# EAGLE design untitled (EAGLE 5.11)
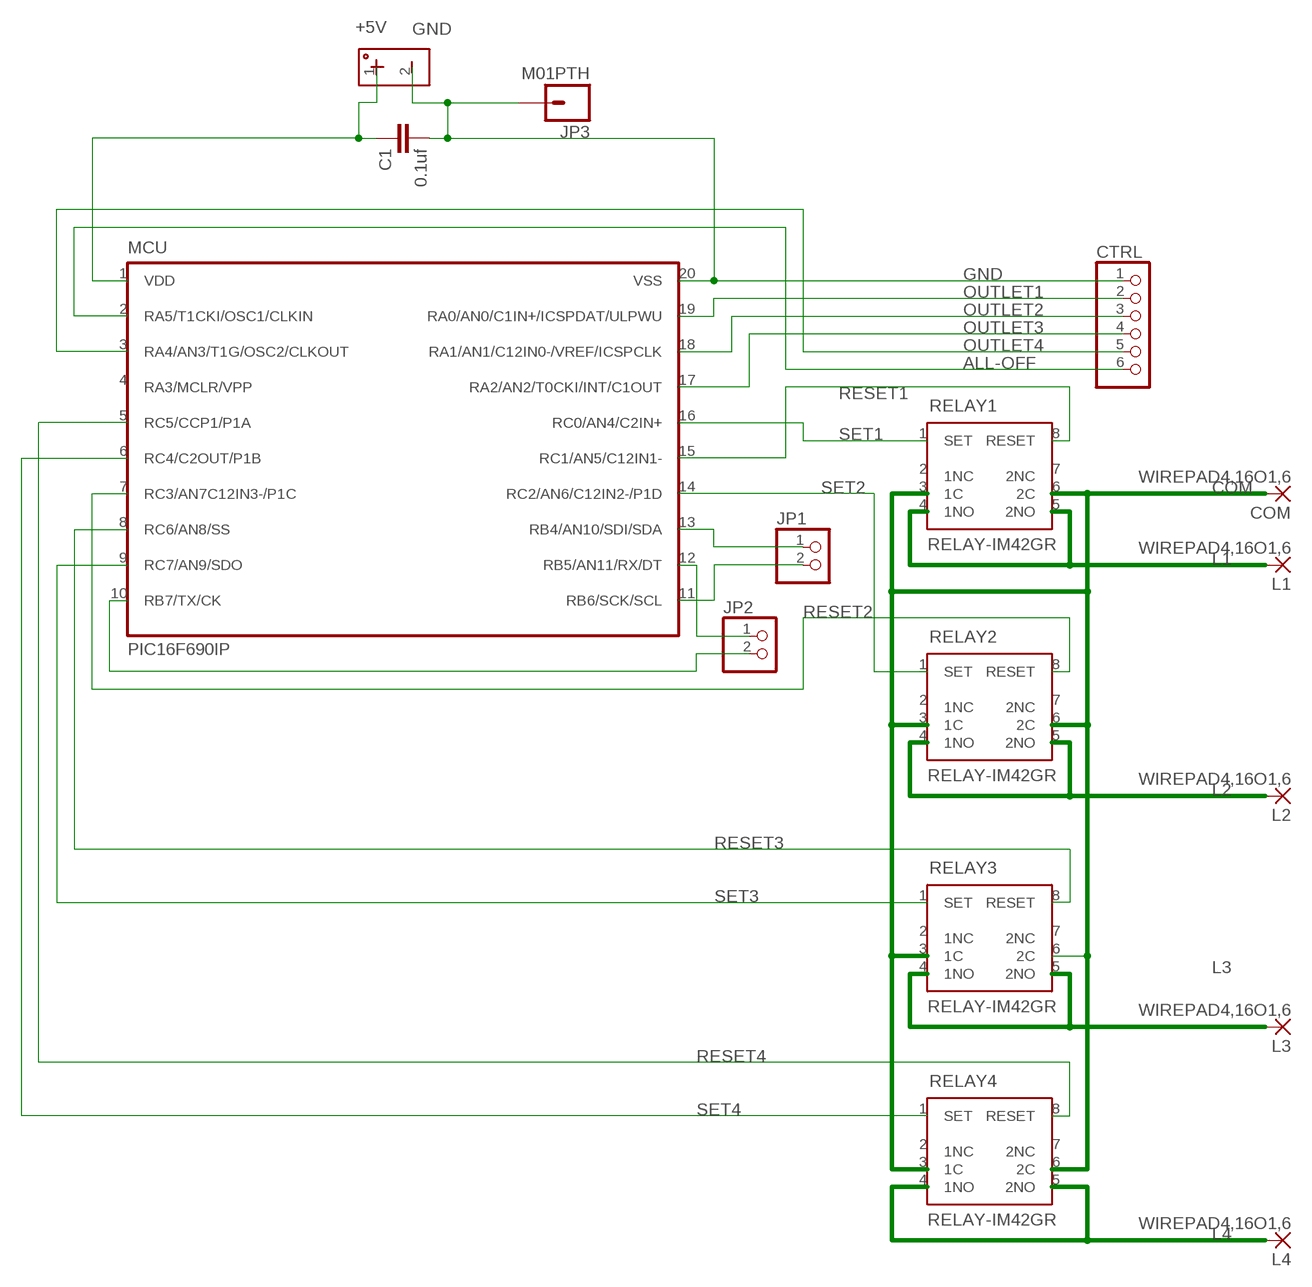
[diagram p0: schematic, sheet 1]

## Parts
+5V  HEADER-POWER  [HEADER-POWER-PTH]
C1  0.1uf  C-EU025-025X050  [C025-025X050]
COM  WIREPAD4,16O1,6  [4,16O1,6]
CTRL  PINHD-1X6  [1X06]
JP1  PINHD-1X2  [1X02]
JP2  PINHD-1X2  [1X02]
JP3  M01PTH  [1X01]
L1  WIREPAD4,16O1,6  [4,16O1,6]
L2  WIREPAD4,16O1,6  [4,16O1,6]
L3  WIREPAD4,16O1,6  [4,16O1,6]
L4  WIREPAD4,16O1,6  [4,16O1,6]
MCU  PIC16F690IP  [DIL20]
RELAY1  RELAY-IM42GR  [RELAY-IM42GR]
RELAY2  RELAY-IM42GR  [RELAY-IM42GR]
RELAY3  RELAY-IM42GR  [RELAY-IM42GR]
RELAY4  RELAY-IM42GR  [RELAY-IM42GR]

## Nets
+5V: +5V.1 C1.1 MCU.1(VDD)
ALL-OFF: CTRL.6 MCU.2(RA5/T1CKI/OSC1/CLKIN)
COM: COM.1(P) RELAY1.3(1C) RELAY1.6(2C) RELAY2.3(1C) RELAY2.6(2C) RELAY3.3(1C) RELAY3.6(2C) RELAY4.3(1C) RELAY4.6(2C)
GND: +5V.2 C1.2 CTRL.1 JP3.1 MCU.20(VSS)
L1: L1.1(P) RELAY1.4(1NO) RELAY1.5(2NO)
L2: L2.1(P) RELAY2.4(1NO) RELAY2.5(2NO)
L3: L3.1(P) RELAY3.4(1NO) RELAY3.5(2NO)
L4: L4.1(P) RELAY4.4(1NO) RELAY4.5(2NO)
N$1: JP1.1 MCU.13(RB4/AN10/SDI/SDA)
N$2: JP2.1 MCU.12(RB5/AN11/RX/DT)
N$3: JP1.2 MCU.11(RB6/SCK/SCL)
N$4: JP2.2 MCU.10(RB7/TX/CK)
OUTLET1: CTRL.2 MCU.19(RA0/AN0/C1IN+/ICSPDAT/ULPWU)
OUTLET2: CTRL.3 MCU.18(RA1/AN1/C12IN0-/VREF/ICSPCLK)
OUTLET3: CTRL.4 MCU.17(RA2/AN2/T0CKI/INT/C1OUT)
OUTLET4: CTRL.5 MCU.3(RA4/AN3/T1G/OSC2/CLKOUT)
RESET1: MCU.15(RC1/AN5/C12IN1-) RELAY1.8(RESET)
RESET2: MCU.7(RC3/AN7C12IN3-/P1C) RELAY2.8(RESET)
RESET3: MCU.8(RC6/AN8/SS) RELAY3.8(RESET)
RESET4: MCU.5(RC5/CCP1/P1A) RELAY4.8(RESET)
SET1: MCU.16(RC0/AN4/C2IN+) RELAY1.1(SET)
SET2: MCU.14(RC2/AN6/C12IN2-/P1D) RELAY2.1(SET)
SET3: MCU.9(RC7/AN9/SDO) RELAY3.1(SET)
SET4: MCU.6(RC4/C2OUT/P1B) RELAY4.1(SET)
Unconnected: MCU.4(RA3/MCLR/VPP) RELAY1.2(1NC) RELAY1.7(2NC) RELAY2.2(1NC) RELAY2.7(2NC) RELAY3.2(1NC) RELAY3.7(2NC) RELAY4.2(1NC) RELAY4.7(2NC)

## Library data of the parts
+5V = trl:HEADER-POWER
C1 = rcl:C-EU: CAPACITOR, European symbol
COM L1-L4 = wirepad:WIREPAD: Wire PAD connect wire on PCB
CTRL = pinhead:PINHD-1X6: PIN HEADER
JP1 JP2 = pinhead:PINHD-1X2: PIN HEADER
JP3 = SparkFun:M01: Header 1
MCU = trl:PIC16F690*: MICROCONTROLLER PIC16F690 18 I/O One 16-bit timer Two 8-bit timer Two comparators Precision internal oscillator-software selectable 8 MHz - 32 KHz SSP w/ I2C Compatible Address mask option EUSART LIN 2.0 Compatible ECCP+ w/ PWM Steering 12 A/D Channels ULPW Enhanced Low Power Timer 1 Timer 1 Gate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
RELAY1-RELAY4 = trl:RELAY-IM42GR

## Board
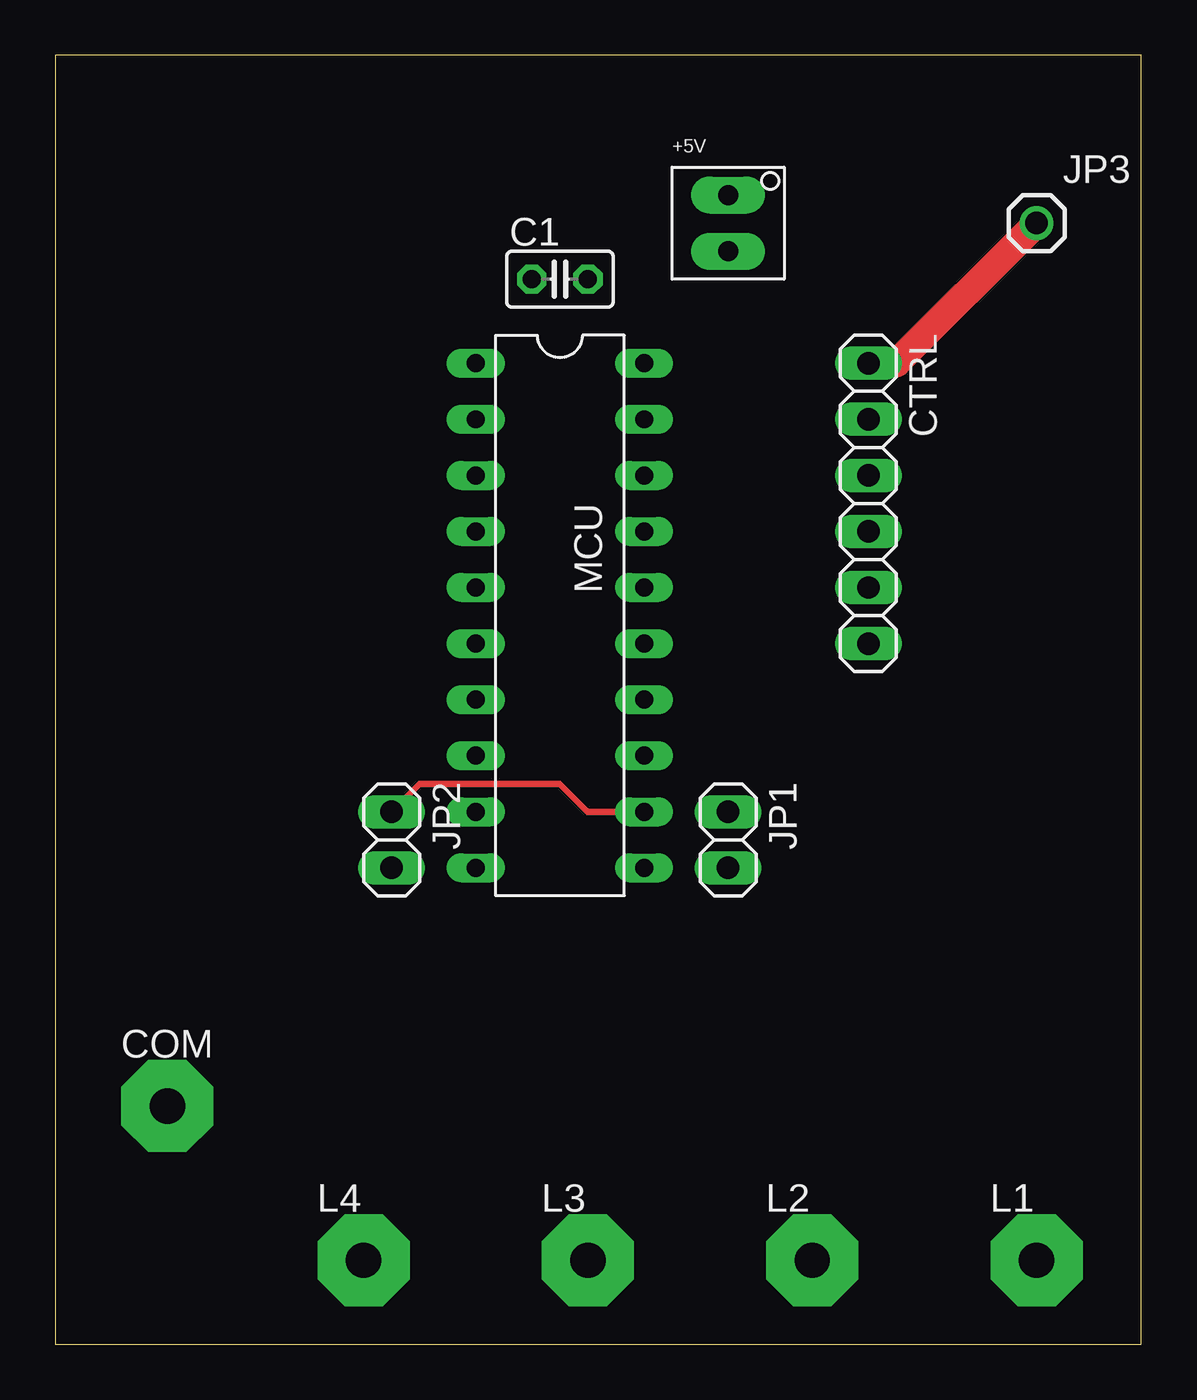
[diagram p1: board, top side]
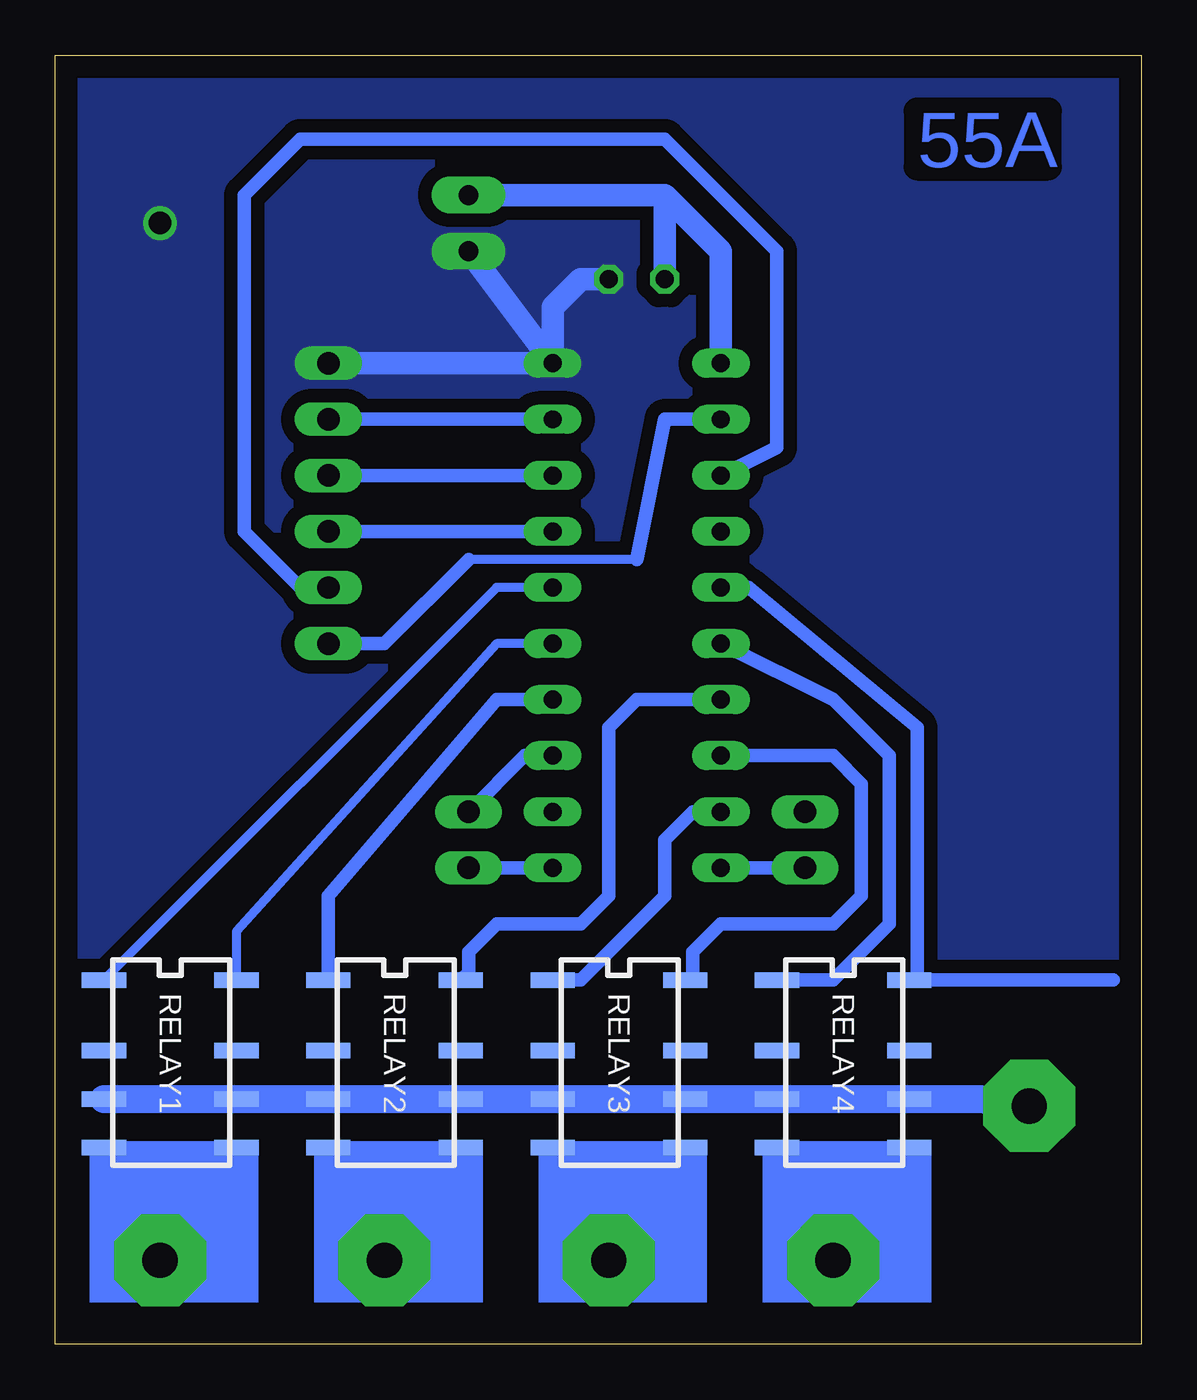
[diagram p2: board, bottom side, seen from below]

Size 49.2 x 58.41 mm. Coordinates in mm from the lower left corner, seen from the top.
Outline: 0,0 49.2,0 49.2,58.41 0,58.41 0,0
Copper layers (1*16): Top 0.035mm / dielectric 1.5mm / Bottom 0.035mm
Design rules "default": minimum track width 10mil, minimum drill 0.6mm, track to track 8mil, track to pad 8mil, pad to pad 8mil, via to via 8mil, smd to smd 8mil, copper to edge 40mil, drill to drill 8mil, minimum pad ring 10mil, minimum via ring 8mil, stop-mask expansion 4mil, vias tented up to drill 0mil, thermal gap 10mil

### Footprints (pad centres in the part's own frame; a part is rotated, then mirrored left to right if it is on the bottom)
HEADER-POWER-PTH = drill 0.9 pad 1.676 long: 1 0,1.27; 2 0,-1.27
C025-025X050 = drill 0.813 octagon: 1 -1.27,0; 2 1.27,0
4,16O1,6 = drill 1.6 pad 4.166 octagon: 1 0,0
1X06 = drill 1.016 long: 1 -6.35,0; 2 -3.81,0; 3 -1.27,0; 4 1.27,0; 5 3.81,0; 6 6.35,0
1X02 = drill 1.016 long: 1 -1.27,0; 2 1.27,0
1X01 = drill 1.016 round: 1 0,0
DIL20 = drill 0.813 long: 1 -11.43,-3.81; 2 -8.89,-3.81; 3 -6.35,-3.81; 4 -3.81,-3.81; 5 -1.27,-3.81; 6 1.27,-3.81; 7 3.81,-3.81; 8 6.35,-3.81; 9 8.89,-3.81; 10 11.43,-3.81; 11 11.43,3.81; 12 8.89,3.81; 13 6.35,3.81; 14 3.81,3.81; 15 1.27,3.81; 16 -1.27,3.81; 17 -3.81,3.81; 18 -6.35,3.81; 19 -8.89,3.81; 20 -11.43,3.81
RELAY-IM42GR = smd 2 x 0.7: 1 0,0; 2 0,-3.2; 3 0,-5.4; 4 0,-7.6; 5 6,-7.6; 6 6,-5.4; 7 6,-3.2; 8 6,0

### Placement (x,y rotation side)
+5V  30.48,50.8 0 top
C1  22.86,48.26 0 top
COM  5.08,10.79 0 top
CTRL  36.83,38.1 270 top
JP1  30.48,22.86 270 top
JP2  15.24,22.86 270 top
JP3  44.45,50.8 0 top
L1  44.45,3.81 0 top
L2  34.29,3.81 0 top
L3  24.13,3.81 0 top
L4  13.97,3.81 0 top
MCU  22.86,33.02 270 top
RELAY1  46.99,16.51 0 bottom
RELAY2  36.83,16.51 0 bottom
RELAY3  26.67,16.51 0 bottom
RELAY4  16.51,16.51 0 bottom

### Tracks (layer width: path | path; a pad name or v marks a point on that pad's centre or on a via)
+5V
  Bottom 1.016: 21.59,52.07 C1.1 | 21.59,52.07 +5V.1 | MCU.1 19.05,49.53 21.59,52.07
ALL-OFF
  Bottom 0.406: 22.86,35.56 30.48,35.56
  Bottom 0.61: CTRL.6 34.29,31.75 30.48,35.56 | 22.86,35.56 21.59,41.91 MCU.2
COM
  Bottom 0.813: RELAY1.3 RELAY1.6
  Bottom 1.27: RELAY1.3 RELAY2.3 RELAY2.6 RELAY3.3 RELAY3.6 RELAY4.3 RELAY4.6 7.3,11.11 COM.1
GND
  Top 1.27: CTRL.1 38.1,44.45 JP3.1
  Bottom 1.016: MCU.20 +5V.2 | C1.2 25.4,48.26 26.67,46.99 MCU.20 | MCU.20 CTRL.1
  pour Bottom (isolate 0.61, no thermals): 0,58.42 50.8,58.42 50.8,0 0,0
L1
  Bottom 0.61: RELAY1.5 RELAY1.4 46.99,6.35 L1.1
L2
  Bottom 0.61: RELAY2.5 RELAY2.4 36.83,6.35 L2.1
L3
  Bottom 0.61: RELAY3.5 RELAY3.4 26.67,6.35 L3.1
L4
  Bottom 0.61: RELAY4.5 RELAY4.4 16.51,6.35 L4.1
N$1
  Bottom 0.61: MCU.13 27.94,26.67 JP1.1
N$2
  Top 0.305: MCU.12 24.13,24.13 22.86,25.4 16.51,25.4 JP2.1
N$3
  Bottom 0.61: MCU.11 JP1.2
N$4
  Bottom 0.61: JP2.2 MCU.10
OUTLET1
  Bottom 0.61: MCU.19 CTRL.2
OUTLET2
  Bottom 0.61: MCU.18 CTRL.3
OUTLET3
  Bottom 0.61: MCU.17 CTRL.4
OUTLET4
  Bottom 0.61: CTRL.5 38.1,34.29 40.64,36.83 40.64,52.07 38.1,54.61 21.59,54.61 16.51,49.53 16.51,40.64 MCU.3
RESET1
  Bottom 0.406: RELAY1.8 40.99,18.7 29.21,31.75 MCU.15
RESET2
  Bottom 0.61: MCU.7 22.86,29.21 24.13,27.94 24.13,20.32 25.4,19.05 29.21,19.05 30.48,17.78 30.48,16.86 RELAY2.8
RESET3
  Bottom 0.61: RELAY3.8 20.32,16.51 20.32,17.78 19.05,19.05 13.97,19.05 12.7,20.32 12.7,25.4 13.97,26.67 MCU.8
RESET4
  Bottom 0.61: MCU.5 17.78,34.29 10.16,27.94 10.16,16.51 | 10.16,16.51 RELAY4.8 | 1.27,16.51 10.16,16.51
SET1
  Bottom 0.406: MCU.16 29.21,34.29 RELAY1.1
SET2
  Bottom 0.61: MCU.14 29.21,29.21 36.83,20.32 RELAY2.1
SET3
  Bottom 0.61: RELAY3.1 25.4,16.51 21.59,20.32 21.59,22.86 20.32,24.13 MCU.9
SET4
  Bottom 0.61: RELAY4.1 13.97,16.51 11.43,19.05 11.43,26.67 13.97,29.21 MCU.6
(copper drawn outside any net)
  shapes: Bottom area x4

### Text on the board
Bottom: 55A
